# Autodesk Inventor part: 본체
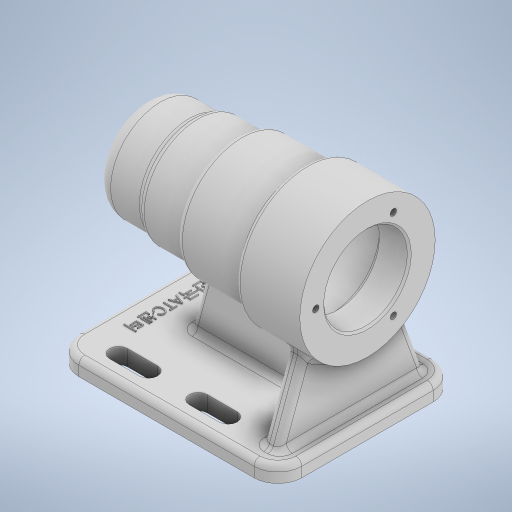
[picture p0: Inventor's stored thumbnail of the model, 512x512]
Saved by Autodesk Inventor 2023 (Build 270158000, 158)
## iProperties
Created: 2022-07
Part Number: 본체
Material: 일반
Document SubType Name: Modeling
Designer: owner
Density: 1 g/cm^3
Appearance: 기본값
Author: owner
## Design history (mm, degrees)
sketch "스케치1"
  geometry: L1 (-44, 45)-(44, 45); L2 (56, 33)-(56, -33); L3 (44, -45)-(-44, -45); L4 (-56, -33)-(-56, 33); L5 (56, 45)-(-56, -45); L6 (56, 0)-(-56, 0); L7 (0, -45)-(0, 45); A1 r 12 centre (44, -33) between (44, -45) and (56, -33); A2 r 12 centre (44, 33) between (56, 33) and (44, 45); A3 r 12 centre (-44, 33) between (-44, 45) and (-56, 33); A4 r 12 centre (-44, -33) between (-56, -33) and (-44, -45); 1 further point
  constraints: 14 end point, 8 point on circle, 8 tangent, 5 midpoint, 4 centre point, 4 point on line, 3 equal radius, 2 parallel, 1 horizontal, 1 perpendicular
  dimensions: "d2" = 12 radius of A1; "d15" = 112 distance between parallel lines of L4 L2; "d16" = 90 distance between parallel lines of L1 L3
extrude "돌출1" new body sketch "스케치1" distance "d17" = 8; taper "d18" = 0 deg
sketch "스케치2"
  geometry: L1 (-32, 87)-(-32, 89); L2 (-32, 89)-(-10, 89); L3 (-10, 89)-(-10, 92); L4 (-10, 92)-(24, 92); L5 (24, 92)-(24, 96); L6 (24, 96)-(56, 96); L7 (56, 96)-(56, 83); L8 (56, 83)-(41, 83); L9 (41, 83)-(41, 83); L10 (38, 86)-(-10, 86); L11 (-13, 83)-(-13, 83); L12 (-13, 83)-(-24.7, 83); L13 (-25, 82.7)-(-25, 79.5); L14 (-25, 79.5)-(-42.7, 79.5); L15 (-43, 79.2)-(-43, 78); L16 (-56, 62)-(56, 62); L17 (-32, 87)-(-56, 87); L18 (-56, 87)-(-56, 62); L19 (-44, 0)-(44, 0) reference; L20 (56, 0)-(56, -8) reference; L21 (-56, 62)-(-50, 62); L22 (-43, 78)-(-46.7, 78); L23 (-47, 77.7)-(-47, 73.5); L24 (-47, 73.5)-(-47, 73.5); L25 (-50, 70.5)-(-50, 62); A1 r 3 centre (38, 83) between (41, 83) and (38, 86); A2 r 3 centre (-10, 83) between (-10, 86) and (-13, 83); A3 r 0.3 centre (-24.7, 82.7) between (-24.7, 83) and (-25, 82.7); A4 r 0.3 centre (-42.7, 79.2) between (-42.7, 79.5) and (-43, 79.2); A5 r 0.3 centre (-46.7, 77.7) between (-46.7, 78) and (-47, 77.7); A6 r 3 centre (-47, 70.5) between (-47, 73.5) and (-50, 70.5); 7 further points
  constraints: 46 end point, 16 perpendicular, 15 point on line, 12 point on circle, 12 tangent, 6 centre point, 3 horizontal, 2 equal radius, 1 collinear, 1 vertical
  dimensions: "d19" = 15 distance between parallel lines of L7 L9; "d20" = 54 distance between parallel lines of L9 L11; "d21" = 12 distance between parallel lines of L11 L13; "d22" = 18 distance between parallel lines of L13 L15; "d25" = 34 distance between parallel lines of L6 L16; "d26" = 24 distance between parallel lines of L10 L16; "d27" = 21 distance between parallel lines of L8 L16; "d30" = 17.5 distance between parallel lines of L14 L16; "d32" = 27 distance between parallel lines of L2 L16; "d33" = 30 distance between parallel lines of L16 L4; "d35" = 112 distance between parallel lines of L7 L18; "d36" = 80 distance between parallel lines of L18 L5; "d37" = 46 distance between parallel lines of L18 L3; "d38" = 24 distance between parallel lines of L18 L1; "d39" = 62 distance between parallel lines of L16 L19; "d40" = 25 distance between parallel lines of L16 L17; "d41" = 3 radius of A1; "d42" = 0.3 radius of A3; "d49" = 4 distance of L15.end point (-47, 78); "d50" = 3 distance of L23.end point (-50, 73.5); "d51" = 16 distance between parallel lines of L16 L22; "d52" = 11.5 distance between parallel lines of L16 L24; "d53" = 0.3 radius of A5 (derived); "d54" = 3 radius of A6
revolve "회전2" sketch "스케치2" stored, may be unused: angle "d55" = 90 deg
sketch "스케치5" dims "d64" = 52
  geometry: L1 (0, 0)-(17, 29.445); L2 (0, 0)-(0, 34); C1 r 8.5 at (0, 0) reference; C2 r 21 at (0, 0) reference; 4 further points
  constraints: 4 end point, 1 coincident, 1 point on line, 1 vertical, 1 vertical alignment, 6 other
  dimensions: "d65" = 30 deg angle of L1 L2
hole "구멍1" sketch "스케치5" at (13, 22.517) diameter "d66" = 3.242; stored, may be unused: countersink angle "d70" = 90 deg, drill point angle "d72" = 118 deg; dims "d67" = 8, "d68" = 4, "d69" = 2, "d71" = 11
fillet "모깎기1" dims "d76" = 2
sketch "스케치6"
  geometry: L1 (-36, 33)-(-21, 33); L2 (-36, 28.5)-(-21, 28.5); L3 (-21, 37.5)-(-36, 37.5); L4 (-36, -33)-(-21, -33); L5 (-36, -37.5)-(-21, -37.5); L6 (-21, -28.5)-(-36, -28.5); L7 (-56, -33)-(-56, 33) reference; L8 (4, 33)-(19, 33); L9 (4, 28.5)-(19, 28.5); L10 (19, 37.5)-(4, 37.5); L11 (4, -33)-(19, -33); L12 (4, -37.5)-(19, -37.5); L13 (19, -28.5)-(4, -28.5); A1 r 4.5 centre (-36, 33) between (-36, 37.5) and (-36, 28.5); A2 r 4.5 centre (-21, 33) between (-21, 28.5) and (-21, 37.5); A3 r 4.5 centre (-36, -33) between (-36, -28.5) and (-36, -37.5); A4 r 4.5 centre (-21, -33) between (-21, -37.5) and (-21, -28.5); A5 r 4.5 centre (4, 33) between (4, 37.5) and (4, 28.5); A6 r 4.5 centre (19, 33) between (19, 28.5) and (19, 37.5); A7 r 4.5 centre (4, -33) between (4, -28.5) and (4, -37.5); A8 r 4.5 centre (19, -33) between (19, -37.5) and (19, -28.5); 5 further points
  constraints: 32 end point, 16 point on circle, 16 tangent, 8 centre point, 4 horizontal, 4 midpoint, 4 parallel
  dimensions: "d78" = 33 vertical distance of point (0, 0) point (-28.5, 33); "d79" = 33 vertical distance of point (-28.5, -33) point (0, 0); "d80" = 15 distance of L4.end L4.start; "d81" = 15 distance of L1.end L1.start; "d84" = 9 distance between parallel lines of L5 L6; "d85" = 9 distance between parallel lines of L2 L3; "d86" = 25 distance of L11.start L4.end; "d87" = 25 distance of L8.start L1.end; "d88" = 9 distance between parallel lines of L9 L10; "d89" = 9 distance between parallel lines of L12 L13; "d90" = 15 distance of L11.end L11.start; "d91" = 15 distance of L8.end L8.start; "d92" = 33 vertical distance of L8.start point (0, 0); "d93" = 33 vertical distance of L11.start point (0, 0); "d100" = 20 distance from line of L1.start L7; "d101" = 20 distance from line of L7 L4.start
extrude "돌출2" cut sketch "스케치6" distance "d94" = 10; taper "d95" = 0 deg
node "작업 평면1"
sketch "스케치10"
  geometry: L1 (0, 37.5)-(0, 28.5) reference; L2 (0, -33)-(0, 33) reference; L3 (0, -45)-(0, -33) reference; L4 (37.342, 23.409)-(0, 37); L5 (0, 45)-(-8, 45) reference; L6 (37.342, -23.409)-(0, -37); L7 (0, -45)-(-8, -45) reference; A1 r 34 centre (62, 0) between (37.342, 23.409) and (37.342, -23.409) reference; 1 further point
  constraints: 4 end point, 2 point on circle, 2 point on line, 1 midpoint
  dimensions: "d115" = 8 distance from line of L4.end L5; "d116" = 8 distance from line of L7 L6.end; "d117" = 110 deg angle of L6 L3; "d118" = 110 deg angle of L1 L4
extrude "돌출4" join sketch "스케치10" distance "d119" = 8; taper "d120" = 0 deg
sketch "스케치11"
  geometry: L1 (-29, 0)-(-19.279, 36.279); L2 (44, 0)-(-44, 0) reference; L3 (48, 0)-(48, 37.342) reference; L4 (40, 0)-(48, 0) reference; L5 (40, 37.342)-(40, 0) reference; L6 (48, 37.342)-(40, 37.342) reference; L7 (-19.279, 36.279)-(40, 36.279); 4 further points
  constraints: 4 end point, 3 point on line, 1 perpendicular
  dimensions: "d121" = 105 deg angle of L1 L2; "d122" = 77 distance of L3.start L1.start; "d142" = 59.27895 distance of L1.end L7.end
  node "투영된 루프1"
fillet "모깎기3" dims "d125" = 3
fillet "모깎기4" dims "d126" = 3
sketch "스케치12"
  geometry: L1 (-56, -33)-(-56, 33) reference; 2 further points
  constraints: 1 horizontal alignment, 1 other
  dimensions: "d127" = 12 distance from line of L1 point (-44, 0)
feature "엠보싱1" sketch "스케치12" dims "d19" = 15, "d20" = 54, "d21" = 12, "d22" = 18, "d25" = 34, "d26" = 24, "d27" = 21, "d30" = 17.5, "d32" = 27, "d33" = 30, "d35" = 112, "d36" = 80, "d37" = 46, "d38" = 24, "d39" = 62, "d40" = 25, "d41" = 3, "d42" = 0.3, "d49" = 4, "d50" = 3, "d51" = 16, "d52" = 11.5, "d53" = 0.3 (derived), "d54" = 3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
chamfer "모따기1" distance "d130" = 1; stored, may be unused: second distance "d131" = 2, angle "d132" = 45 deg
extrude "돌출6" join sketch "스케치11" stored distance "d134" = 8; taper "d135" = 0 deg
fillet "모깎기5" dims "d136" = 3
fillet "모깎기6" dims "d137" = 3
fillet "모깎기7" dims "d138" = 3
fillet "모깎기9" dims "d140" = 8
fillet "모깎기10" dims "d141" = 3
node "솔리드1"
pattern_circular "원형 패턴1" dims angle "d74" = 360 deg
feature "A9D066F2-1C7D-4E18-AEED-F7BC21143FA4" dims "d66" = 3.242, "d67" = 8, "d68" = 4, "d69" = 2, "d70" = 90 deg, "d71" = 11, "d72" = 118 deg
other parameters: "d110" = 48
